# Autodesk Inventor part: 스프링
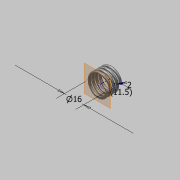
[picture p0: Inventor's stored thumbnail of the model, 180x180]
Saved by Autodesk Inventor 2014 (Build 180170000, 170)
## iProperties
Created: 2015-04
Part Number: 스프링
Material: 강철, 탄소
Document SubType Name: Modeling
Designer: Administrator
Density: 7.87 g/cm^3
Appearance: 반연마
Mass: 4.78775 g
Surface Area: 12.5241 cm^2
Volume: 0.608355 cm^3
Author: Administrator
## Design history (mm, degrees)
sketch "스케치2"
  geometry: L1 (0, 11.5)-(-8, 11.5); L2 (-8, 11.5)-(-8, 0); L3 (-8, 0)-(0, 0); L4 (0, 0)-(0, 11.5); C1 r 1 at (-8, 0); 1 further point
  constraints: 8 end point, 2 coincident, 2 parallel, 1 centre point, 1 horizontal, 1 perpendicular
  dimensions: "d0" = 16 diameter of L2 L4; "d1" = 11.50049 distance between parallel lines of L1 L3 (derived); "d2" = 2 diameter of C1
feature "코일1" pitch "d3" = 10; turns "d5" = 4; dims "d4" = 11.50049 (= d1), "d6" = 0, angle "d7" = 90 deg, angle "d8" = 90 deg, "d9" = 0, "d10" = 0
sketch "스케치3"
  geometry: L1 (9, 0)-(7, 0) reference; 1 further point
  constraints: 1 horizontal alignment
extrude "돌출1" cut sketch "스케치3" stored distance "d11" = 10; taper "d12" = 0 deg
node "작업 평면1"
sketch "스케치4"
  geometry: L1 (7, 0)-(9, 0) reference; 1 further point
  constraints: 1 horizontal alignment
extrude "돌출2" cut sketch "스케치4" stored distance "d13" = 10; taper "d14" = 0 deg
node "솔리드1"
node "절단 모서리 투영1"
node "절단 모서리 투영2"
